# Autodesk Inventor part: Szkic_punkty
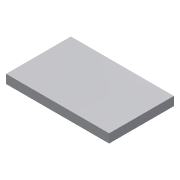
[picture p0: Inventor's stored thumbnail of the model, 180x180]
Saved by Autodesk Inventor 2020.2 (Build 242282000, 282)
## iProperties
Created: 2015-05
Part Number: Szkic_punkty
Material: Ogólny
Document SubType Name: Modeling
Designer: F.Stasiak
Density: 1 g/cm^3
Appearance: Biały
Manager: www.cadconsulting.pl
Company: Fabian Stasiak CAD Consulting
Author: F.Stasiak
Subject: Zbiór ćwiczeń. Autodesk Inventor 2020. Kurs podstawowy
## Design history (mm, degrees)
sketch "Szkic1"
  geometry: L1 (0, 0)-(350, 0); L2 (350, 0)-(350, 220); L3 (350, 220)-(0, 220); L4 (0, 220)-(0, 0)
  constraints: 8 end point, 2 parallel, 1 horizontal, 1 perpendicular
  dimensions: "d0" = 350 distance of L3.end L2.end; "d1" = 220 distance of L2.end L1.end
extrude "Wyciągnięcie proste1" new body sketch "Szkic1" distance "d16" = 30; taper "d17" = 0 deg
feature "Skorupa1" dims "d18" = 3
node "Bryła1"
